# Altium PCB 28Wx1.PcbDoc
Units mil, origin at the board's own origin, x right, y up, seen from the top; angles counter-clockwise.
Board outline 11435 x 885 mil, 2 copper layers (Top Layer, Bottom Layer); 107 components, 53 nets, 262 pads, 0 vias.
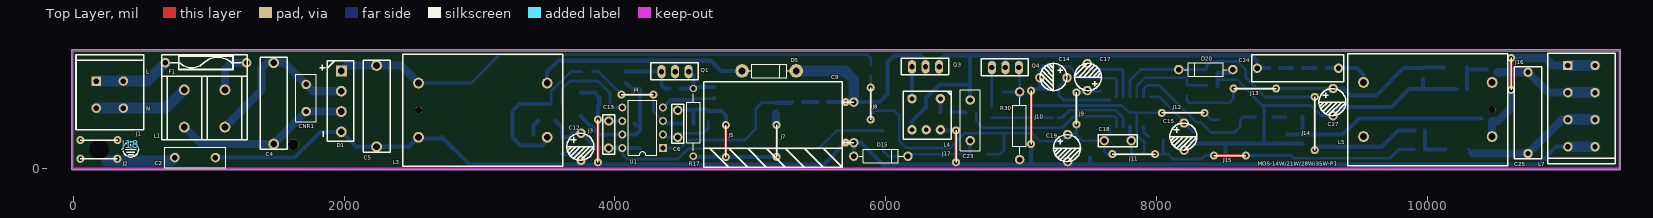
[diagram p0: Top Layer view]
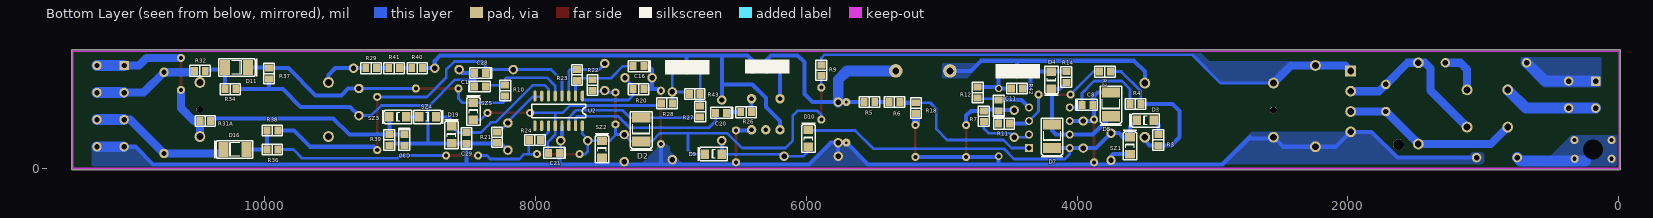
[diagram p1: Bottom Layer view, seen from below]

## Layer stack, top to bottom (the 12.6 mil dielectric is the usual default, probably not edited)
Top Layer: signal copper 1.4
Dielectric: dielectric 12.6, FR-4, Dk 4.8
Bottom Layer: signal copper 1.4

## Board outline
-10,-10 11425,-10 11425,875 -10,875

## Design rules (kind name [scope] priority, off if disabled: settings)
Clearance [All] p1: gap=10
ComponentClearance [All] p1 off: gap=10 collisioncheckmode=3 verticalgap=10 showdistances=FALSE
Height [All] p1 off: minheight=0 maxheight=1000 prefheight=500
PolygonConnect [All] p1: connectstyle=Direct reliefconductorwidth=10 reliefentries=4 polygonreliefangle="90 Angle"
RoutingVias [All] p1: holewidth=28 width=50 viastyle="Through Hole" minholewidth=28 minwidth=50 maxholewidth=28 maxwidth=50
SolderMaskExpansion [All] p1: expansion=4
TestPointUsage [All] p1: valid=0 allowmultiple=FALSE
Testpoint [All] p1: side=15 testpointundercomponent=TRUE minsize=40 maxsize=100 preferedsize=60 minholesize=0 maxholesize=40 preferedholesize=32 testpointgrid=1 style=1023 order=0-112345678
Width [All] p1: maxlimit=80 minlimit=10 preferedwidth=10 toplayer_minwidth=20 toplayer_maxwidth=20 toplayer_prefwidth=20 bottomlayer_prefwidth=30 minimp=50.000000 maximp=50.000000 favimp=50.000000
17 further rules are at their usual default settings.

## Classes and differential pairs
component class 20081212SMD: C1 C2 C4 C5 C6 C8 C9 C11 C12 C13 C14 C15 C16 C17 C18 C19 C20 C21 C23 C24 C25 C27 C28 C29 C30 CNR1 D1 D2 D3 D4 D5 D7 D8 D9 D10 D11 D15 D16 D19 D20 F1 J1 J2 L1 L3 L4 L5 L7 Q1 Q3 Q4 R2 R3 R4 R5 R6 R7 R9 R10 R11 R12 R14 R17 R18 R20 R21 R22 R23 R24 R26 R27 R28 R29 R30 R31A R32 R34 R36 R37 R38 R39 R40 R41 R42 R43 SZ1 SZ2 SZ3 SZ4 SZ5 U1 U2

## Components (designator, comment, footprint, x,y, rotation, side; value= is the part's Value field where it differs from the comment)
C1 "Cap" C0805A 8410,605 r180 bottom
C2 "Cap Y1" RAD-0.3 900,80 r180 top
C4 "Cap X1" RAD0.6B#1 1480,180 r90 top
C5 "CAP" RAD0.6B#1 2240,160 r90 top
C6 "CAP" RAD0.2B 4465,430 r270 top
C8 "CAP" C0805A 3925,470 r180 bottom
C9 "Cap2" RB.3/.6A 5765,490 r0 top locked
C11 "CAP" C0805A 4580,465 r90 bottom
C12 "CAP" RB.2/.2 3750,160 r0 top
C13 "CAP" RAD0.2B 3955,350 r270 top
C14 "Cap" RB.2/.2 7240,670 r270 top
C15 "Cap" RB.2/.2 8205,235 r0 top
C16 "Cap" C0805A 7240,755 r0 bottom
C17 "Cap2" RB.2/.2 7490,675 r180 top
C18 "CAP" RAD0.2B 7815,205 r180 top
C19 "Cap" RB.2/.2 7345,150 r0 top
C20 "CAP" C0805A 6630,410 r0 bottom
C21 "CAP" C0805A 7865,115 r0 bottom
C23 "CAP" RAD-0.3 6625,355 r270 top
C24 "CAP" RAD0.6B#2 9345,740 r180 top
C25 "CAP" RAD0.6B#2 10745,710 r270 top
C27 "Cap2" RB.2/.2 9305,490 r0 top
C28 "Cap" C0805A 8410,705 r0 bottom
C29 "Cap" C0805A 8510,225 r90 bottom
C30 "Cap" C0805A 8970,210 r270 bottom
CNR1 "CNR" RAD-0.2 1720,520 r270 top
D1 "DIODEx4" SIP4C 1980,720 r270 top
D2 "Diode 1N5819" CD4532-1812A 7220,280 r270 bottom
D3 "DIODE" CD3216-1206A 3495,355 r0 bottom
D4 "Comment" CD3216-1206A 4190,655 r270 bottom
D5 "HIGH EFFICIENCY DIODES" DIODE-0.4#1 5140,720 r0 top
D7 "Diode 1N5819" CD4532-1812A 4185,230 r270 bottom
D8 "Diode 1N5819" CD4532-1812A 3750,465 r270 bottom
D9 "DIODE" CD3216-1206A 6685,105 r0 bottom
D10 "DIODE" CD3216-1206A 5985,220 r90 bottom
D11 "DIODE" CD4532-1810 10200,745 r180 bottom
D15 "FFAST RECOVERY RECTIFIER" DIODE-0.4#2 5965,90 r0 top
D16 "Surface Mount Glass Passivated Rectifier" CD4532-1810 10230,140 r0 bottom
D19 "DIODE" CD3216-1206A 8620,245 r90 bottom
D20 "HIGH EFFICIENCY DIODES" DIODE-0.4#2 8365,730 r180 top
F1 "3.15A/250V" FUSE0.6 680,780 r0 top
J1 "Header 2" IDC4-3.8MM 20,840 r270 top
J2 "PAD" GND1 190,140 r180 top
J3 "Comment" JUMP_8MM 3875,45 r90 top
J4 "Comment" JUMP_6MM 4285,545 r180 top
J5 "Comment" JUMP_6MM 4820,320 r270 top
J7 "Comment" JUMP_6MM 5195,85 r90 top
J8 "Comment" JUMP_6MM 5890,360 r90 top
J9 "Comment" JUMP_6MM 7410,325 r90 top
J10 "Comment" JUMP_10MM 7075,180 r90 top
J11 "Comment" JUMP_8MM 7675,105 r0 top
J12 "Comment" JUMP_8MM 8040,410 r0 top
J13 "Comment" JUMP_8MM 8570,590 r0 top
J14 "Comment" JUMP_10MM 9170,135 r90 top
J15 "Comment" JUMP_6MM 8425,95 r0 top
J16 "Comment" JUMP_6MM 10620,580 r90 top
J17 "Comment" JUMP_6MM 6520,45 r90 top
J18 "Comment" GND2 425,180 r0 top
L1 "INDUCTOR_EMI" EE1414H 820,580 r0 top
L3 "INDUCTOR2:2_3_1" EE2520H 2435,15 r0 top
L4 "INDUCTOR2:2" EE0808 6405,515 r180 top
L5 "INDUCTOR2.1_1" EE2720H 9415,20 r0 top locked
L7 "TUBES1" IDC8-3.8MM 11040,760 r270 top locked
Q1 "MOSFET-N" TO-220D 4445,715 r0 top
Q3 "MOSFET-N" TO-220D 6295,750 r0 top
Q4 "MOSFET-N" TO-220D 6885,745 r0 top
R2 "RES1" 2012[0805]A 3795,715 r0 bottom
R3 "RES1" 2012[0805]A 3400,210 r90 bottom
R4 "RES1" 2012[0805]A 3570,475 r0 bottom
R5 "RES1" 2012[0805]A 5535,490 r0 bottom
R6 "RES1" 2012[0805]A 5350,490 r0 bottom
R7 "Res1" 2012[0805]A 4690,385 r270 bottom
R9 "RES1" 2012[0805]A 5890,725 r90 bottom
R10 "RES1" 2012[0805]A 8225,575 r90 bottom
R11 "RES1" 2012[0805]A 4540,330 r0 bottom
R12 "RES1" 2012[0805]A 4735,560 r90 bottom
R14 "RES1" 2012[0805]A 4080,675 r90 bottom
R17 "RES1" AXIAL-0.5#1 4580,340 r90 top
R18 "RES1" 2012[0805]A 5190,445 r90 bottom
R20 "RES1" 2012[0805]A 7240,585 r0 bottom
R21 "RES1" 2012[0805]A 8285,230 r90 bottom
R22 "RES1" 2012[0805]A 7580,615 r270 bottom
R23 "RES1" 2012[0805]A 7695,690 r90 bottom
R24 "RES1" 2012[0805]A 8005,210 r180 bottom
R26 "RES1" 2012[0805]A 6445,415 r0 bottom
R27 "RES1" 2012[0805]A 6785,420 r90 bottom
R28 "RES1" 2012[0805]A 7030,480 r0 bottom
R29 "Res1" 2012[0805]A 9215,740 r180 bottom
R30 "RES1" AXIAL-0.5#2 6990,315 r90 top
R31A "RES1" 2012[0805]A 10440,350 r0 bottom
R32 "RES1" 2012[0805]A 10480,720 r180 bottom
R34 "RES1" 2012[0805]A 10255,585 r0 bottom
R36 "RES1" 2012[0805]A 9945,140 r180 bottom
R37 "RES1" 2012[0805]A 9970,700 r90 bottom
R38 "RES1" 2012[0805]A 9945,280 r180 bottom
R39 "RES1" 2012[0805]A 9080,210 r90 bottom
R40 "Res1" 2012[0805]A 8875,740 r0 bottom
R41 "Res1" 2012[0805]A 9045,740 r180 bottom
R42 "RES1" 2012[0805]A 4445,590 r0 bottom
R43 "RES1" 2012[0805]A 6825,550 r0 bottom
SZ1 "Zener" CD3216-1206A 3610,165 r90 bottom
SZ2 "Zener" CD3216-1206A 7510,140 r90 bottom
SZ3 "Zener" CD3216-1206A 9015,380 r0 bottom
SZ4 "Zener" CD3216-1206A 8800,380 r180 bottom
SZ5 "Zener" CD3216-1206A 8460,420 r90 bottom
U1 "59039" DIP-8 4205,300 r90 top
U2 "IC" DIP16A 7655,535 r0 bottom

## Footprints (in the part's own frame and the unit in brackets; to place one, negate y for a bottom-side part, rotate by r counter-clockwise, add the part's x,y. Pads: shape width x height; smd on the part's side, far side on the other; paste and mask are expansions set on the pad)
2012[0805]A [mm] "Chip Resistor; Body 2.0 x 1.3 mm (LxW typ)"
  rect 1.3x1.5 smd: 1(-1.016,0) 2(1.016,0)
  silkscreen extent -1.91,-1.02 1.91,1.02
AXIAL-0.5#1 [mm] "Variable Resistor; 2 Leads"
  round 1.4 hole 0.85: 1(-6.35,0) 2(6.35,0)
  silkscreen extent -5.33,-1.27 5.33,1.27
AXIAL-0.5#2 [mm] "Semiconductor Resistor; 2 Leads"
  round 1.778 hole 1.016: 1(-6.35,0) 2(6.35,0)
  silkscreen extent -5.33,-1.27 5.33,1.27
C0805A [mm] "Chip Capacitor; Body 2.0 x 1.2 mm (LxW typ)"
  rect 1.3x1.5 smd: 1(-1.016,0) 2(1.016,0)
  silkscreen extent -2.16,-1.02 1.91,1.02
CD3216-1206A [mm] "Chip Diode; Body 3.2 x 1.6 mm (LxW typ)"
  rect 1.6x1.8 smd: 1(-1.524,0) 2(1.651,0)
  silkscreen extent -2.54,-1.27 2.92,1.27
CD4532-1810 [mm] "Chip Diode; Body 4.5 x 3.2 mm (LxW typ)"
  rect 1.9x2.8 smd: 1(-2.413,0) 2(1.95,0)
  silkscreen extent -3.56,-1.65 3.56,1.65
CD4532-1812A [mm] "Chip Diode; Body 4.5 x 3.2 mm (LxW typ)"
  rect 1.9x3.4 smd: 1(-2.413,0) 2(2.032,0)
  silkscreen extent -3.56,-2.03 3.68,2.03
DIODE-0.4#1 [mil] "Tunnel Diode - Dependent Source Model; 2 Leads"
  round 100 hole 50: 1(-200,0) 2(200,0)
  silkscreen extent -160,-50 160,50
DIODE-0.4#2 [mil] "Tunnel Diode - Dependent Source Model; 2 Leads"
  round 70 hole 40: 1(-200,0) 2(200,0)
  silkscreen extent -160,-50 160,50
DIP16A [mil]
  oval 24x80 smd: 0(350,0) 0(350,220) 1(0,0) 2(50,0) 3(100,0) 4(150,0) 5(200,0) 6(250,0) 7(300,0) 8(300,220) 9(250,220) 10(200,220) 11(150,220) 12(100,220) 13(50,220) 14(0,220)
  silkscreen extent -25,60 375,160
DIP-8 [mm] "DIP; 8 Leads; Row Spacing 7.62 mm; Pitch 2.54 mm"
  rect 1.5x1.5 hole 0.9: 1(-3.81,-3.81)
  round 1.5 hole 0.9: 2(-1.27,-3.81) 3(1.27,-3.81) 4(3.81,-3.81) 5(3.81,3.81) 6(1.27,3.81) 7(-1.27,3.81) 8(-3.81,3.81)
  silkscreen extent -5.15,-2.65 5.15,2.65
EE0808 [mil]
  round 70 hole 35: 1(0,0) 3(210,0) 4(210,230) 5(105,230) 6(0,230)
  silkscreen extent -80,-55 275,300
EE1414H [mil]
  round 80 hole 50: 1(0,0) 2(0,-275) 3(300,-275) 4(300,0)
  silkscreen extent -165,-370 465,261
EE2520H [mil]
  round 80 hole 50: 1(1065,215) 3(1065,615) 4(115,615) 6(115,215)
  round 50 hole 50: 5(115,415)
  silkscreen extent 0,0 1181,827
EE2720H [mil]
  round 80 hole 50: 1(1065,215) 3(1065,615) 4(115,615) 6(115,215)
  round 50 hole 50: 2(1065,415)
  silkscreen extent 0,0 1181,827
FUSE0.6 [mil]
  round 70 hole 40: 1(0,0) 2(600,0)
  silkscreen extent 40,-50 560,50
GND1 [mil] "GND"
  round 60 hole 145: 0(0,0)
  round 60 hole 30: ""(-137.8,-68.9) ""(-135,68.9) ""(137.8,-68.9) ""(137.8,68.9)
  silkscreen extent -138,-69 138,69
GND2 [mil]
  silkscreen extent -57,-97 57,17
IDC4-3.8MM [mil]
  round 70 hole 40: 1(195,350) 2(395,350) 2(395,150)
  rect 70x70 hole 40: 1(195,150)
  silkscreen extent 0,0 555,500
IDC8-3.8MM [mil]
  round 70 hole 40: 1(0,200) 2(200,200) 2(200,0) 3(400,200) 3(400,0) 4(600,0) 4(600,200)
  rect 70x70 hole 40: 1(0,0)
  silkscreen extent -90,-150 725,350
JUMP_6MM [mil]
  round 60 hole 30: 1(0,0) 2(236.22,0)
  silkscreen extent 0,0 236,0
JUMP_8MM [mil]
  round 60 hole 30: 1(0,0) 2(314.96,0)
  silkscreen extent 0,0 315,0
JUMP_10MM [mil]
  round 60 hole 30: 1(0,0) 2(393.7,0)
  silkscreen extent 0,0 394,0
RAD0.2B [mil]
  round 70 hole 40: 1(0,0) 2(200,0)
  silkscreen extent -45,-45 245,45
RAD0.6B#1 [mil]
  round 80 hole 50: 1(0,0) 2(600,0)
  silkscreen extent -40,-100 640,100
RAD0.6B#2 [mil]
  round 70 hole 40: 1(0,0) 2(600,0)
  silkscreen extent -40,-100 640,100
RAD-0.2 [mil] "Jumper Wire; 2 Leads"
  round 70 hole 40: 1(-100,0) 2(100,0)
  silkscreen extent -175,-75 175,75
RAD-0.3 [mil] "Capacitor; 2 Leads"
  round 70 hole 40: 1(-150,0) 2(150,0)
  silkscreen extent -225,-75 225,75
RB.2/.2 [mil]
  round 70 hole 40: 1(0,100) 2(0,-100)
  silkscreen extent -105,-100 95,100
RB.3/.6A [mil]
  round 70 hole 40: 1(0,0) 2(0,-300)
  silkscreen extent -1110,-480 0,150
SIP4C [mil]
  rect 80x80 hole 50: 1(0,0)
  round 80 hole 50: 2(150,0) 3(300,0) 4(450,0)
  silkscreen extent -75,-160 520,92
TO-220D [mil]
  oval 60x100 hole 40: 1(0,0) 2(-100,0) 3(100,0)
  silkscreen extent -180,-60 170,65

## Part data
C1 C6 C8 C11 C13 C16 C18 C20 C21 C28 C29 C30: "Ceramic Capacitor"
C2: library part CAP, "Y Capacitor"
C4: library part CAP, "BOX Capacitor"
C5: "BOX Capacitor"
C9 C17 C27: "Electrolytic Capacitor"
C12 C14 C15 C19: library part Cap2, "Electrolytic Capacitor"
C23 C24 C25: "POLYPROPYLENE FILM Capacitor"
CNR1: "Varistor"
D1: "Bridge Diode"
D2 D7 D8: library part "Diode 1N4007", "1 Amp General Purpose Rectifier"
D3 D9 D10 D19: "Diode  75V,1A"
D5: library part DIODE, "Diode HIGH EFFICIENCY RECTIFIERS 600V, 3A"
D11: "Diode FAST RECOVERY RECTIFIER 700V,1A"
D15 D16: library part DIODE, "Diode FAST RECOVERY RECTIFIER 700V,1A"
D20: library part DIODE, "Diode HIGH EFFICIENCY RECTIFIERS 600V, 1A"
F1: library part FUSE2, "Fuse"
J1: "Header, 2-Pin"
L1: "EE19H Inductor"
L4: "EE08 Inductor"
L7: "Jumper Wire Pin spacing 3.5mm    235-107/000-009"
Q1: "Transistor, MOSFET  600V, 11A"
Q3 Q4: "Transistor, MOSFET  600V, 6A"
R2 R3 R4 R5 R6 R9 R10 R11 R12 R14 R18 R20 R21 R22 R23 R24 R26 R27 R28 R29 R31A R32 R34 R36 R37 R38 R39 R40 R41 R42 R43: "Resistor 1/4W"
R7: "Resistor"
R17 R30: "Resistor 1W"
SZ1 SZ2: library part "D Zener", "Zener Diode"
SZ3 SZ4 SZ5: library part "D Zener", "Zener Diode 1/4W"
U1: "M8128"
U2: library part M8145, "IC, Ballast Driver"

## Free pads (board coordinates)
  round 80 hole 80: 0(1625,175)
  round 60 hole 20: 0(5705,490) 1(5705,190)

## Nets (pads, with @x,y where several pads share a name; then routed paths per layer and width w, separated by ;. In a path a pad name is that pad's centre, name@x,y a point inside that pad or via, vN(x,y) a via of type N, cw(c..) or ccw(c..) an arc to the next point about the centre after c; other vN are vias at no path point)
GND: C1.1 C2.1 C5.1 C6.1 C8.2 C9.2 C11.1 C12.2 C13.1 C14.2 C15.2 C16.1 C18.1 C19.2 C21.1 C27.2 C28.2 C29.1 C30.2 D1.4 D8.1 D15.1 D19.1 D20.1 J3.1 J3.2 J5.1 J5.2 J7.1 J7.2 J10.1 J10.2 J17.1 J17.2 L3.6 L4.6 L7.4 pad.1 R7.1 R11.2 R17.1 R18.1 R20.1 R21.1 R30.1 R34.1 R37.1 R39.1 SZ1.1 SZ2.1 U1.6 U2.11 | length 18896.5
  Top Layer w20: J3.1 J3.2 ; J5.2 J5.1 ; J7.1 J7.2 ; J17.1 J17.2 ; J10.1 J10.2
  Bottom Layer w20: C21.1@7815,115 C18.1 ; 8450,655 8595,655 8785,465 8795,465 ; 8795,185 8795,465 ; C27.2 9215,390 9140,465 8795,465
  Bottom Layer w30: C2.1 1635,80 1825,270 D1.4 2090,160 C5.1 2480,160 L3.6 ; L3.6@2545,220 2720,220 ; 2725,230 2925,30 4585,30 ; SZ1.1 3735,105 3750,90 C12.2 ; D8.1 3850,560 3885,525 C8.2@3885,475 ; C8.2 C8.2@3885,475 ; U1.6 C13.1 3884.96,350 J3.2 3875,465 C8.2@3885,475 ; C6.1 C11.1@4580,430 ; R11.2 C11.1@4580,430 ; J5.1 4820,390 4785,425 R7.1 4680,435 4585,435 C11.1@4580,430 ; J7.2@5190,326.22 J7.2 ; J7.1@5193.78,83.78 J5.2 4586.22,83.78 R17.1 4580,35 4585,30 ; D15.1 C9.2 ; L4.6 6408.78,281.22 J17.2 ; R30.1 6990,30 ; J10.1 7075,30 ; J10.2@7075,585 7140,585 ; 7140,30 7075,30 ; R20.1 7140,585 ; C16.1 7165,755 7140,730 C14.2 7140,585 ; 7465,30 7405,30 ; SZ2.1 7510,30 ; C18.1@7805,205 U2.11@7805,310 ; C21.1 7825,30 ; C15.2 8255,185 C29.1 ; C1.1 8450,655 C28.2 8545,705 D20.1@8570,730 ; R39.1@9080,180 9075,185 8795,185 D19.1 C29.1 ; C27.2 9370,455 9735,455 9865,585 9970,585 ; R37.1 9970,585 ; R34.1 9970,585 ; L7.4@11040,160 10955,160 10825,30 8515,30 ; 4585,30 5545,30 pad.1 C9.2 ; C9.2 5820,190 5980,30 6990,30 ; 6990,30 7075,30 ; 6990,30 7075,30 ; 7075,30 7405,30 ; 7405,30 7510,30 ; 7510,30 7825,30 ; 7825,30 8515,30 ; C29.1 8510,35 8515,30
  Bottom Layer w60: J7.2@5190,326.22 R18.1
  Bottom Layer w80: L7.4@11045,160 L7.4@11240,160
L: F1.1 J1.1 | length 565.9
  Bottom Layer w80: J1.1@170,645 370,645 545,645 F1.1
N: J1.2 L1.1 | length 705.9
  Bottom Layer w80: J1.2@170,445 370,445 685,445 L1.1
NetC1_2: C1.2 R10.2 U2.5 | length 669
  Bottom Layer w20: U2.5@7855,530 7855,610 7915,670 8215,670 8225,660 R10.2 C1.2@8370,615
NetC2_2: C2.2 J2. J2.0 | length 607.3
  Bottom Layer w30: J2.0@180,120 245,55
  Bottom Layer w80: 245,55 725,55 C2.2
NetC4_1: C4.1 CNR1.2 D1.3 L1.2 | length 1311.2
  Bottom Layer w60: L1.2 945,180 C4.1 CNR1.2 D1.3
NetC5_2: C5.2 D1.1 L3.4 R9.2 | length 4127.8
  Bottom Layer w20: L3.4 2940,630 3150,840 5865,840 5890,815 R9.2
  Bottom Layer w60: D1.1 2020,760 C5.2 2420,760 L3.4
NetC6_2: C6.2 R7.2 U1.2 | length 420.2
  Bottom Layer w20: U1.2 4375,230 C6.2 4495,260 4655,260 4690,295 R7.2
NetC8_1: C8.1 R4.2 U1.5 | length 710.4
  Bottom Layer w20: R4.2 3610,585 3670,645 3875,645 3965,555 C8.1
  Bottom Layer w30: C8.1 3985,450 U1.5
NetC9_1: C9.1 D5.2 pad.0@5705,490 Q3.1 R5.2 | length 1692
  Bottom Layer w30: R5.2 C9.1 5955,490 6015,550 6015,785 6065,835 6260,835 6295,800 Q3.1@6295,740
  Bottom Layer w80: D5.2 5700,720 5765,655 C9.1
NetC11_2: C11.2 R12.1 U1.4 | length 399.9
  Bottom Layer w20: C11.2@4585,515 R12.1@4730,515
  Bottom Layer w30: U1.4 4410,505 C11.2 ; R12.1@4730,515 R12.1
NetC12_1: C12.1 C13.2 D3.2 D7.2 D10.2 SZ1.2 U1.8 | length 2852.3
  Bottom Layer w20: U1.8 4055,105 4090,70 4465,70 4540,145 5505,145 5640,280 5975,280 D10.2@5980,275
  Bottom Layer w30: D3.2 3610,305 SZ1.2 3660,230 3690,260 C12.1 3860,150 C13.2 U1.8 D7.2
NetC14_1: C14.1 R20.2 U2.1 | length 544.4
  Bottom Layer w20: C14.1 7280,610 R20.2 7280,540 7315,505 U2.1@7655,505
NetC15_1: C15.1 R21.2 U2.0@8005,535 U2.7 | length 440.6
  Bottom Layer w20: U2.7@7955,530 8020,530 C15.1@8210,340 ; C15.1 8270,270 R21.2
NetC16_2: C16.2 R22.1 R23.1 U2.2 | length 572.3
  Bottom Layer w20: C16.2 7355,755 7445,665 R23.1@7695,665 ; U2.2@7705,530 R23.1@7705,650
NetC17_2: C17.2 R23.2 U2.3 | length 475.7
  Bottom Layer w20: C17.2@7490,770 7530,730 R23.2 7745,730 7755,720 U2.3@7755,530
NetC20_1: C20.1 R26.2 | length 107.1
  Bottom Layer w30: R26.2 6585,415 C20.1
NetC20_2: C20.2 U2.13 | length 1252.5
  Bottom Layer w20: C20.2 6670,350 ; 6695,325 6670,350 ; U2.13@7705,310 7705,370 7690,385 7390,385 7305,300 6720,300 6670,350
NetC21_2: C21.2 J12.1 J12.2 R28.2 SZ5.1 U2.10 | length 1788.3
  Top Layer w20: J12.1 J12.2
  Bottom Layer w20: R28.2@7070,465 7745,465 7800,410 7855,410 ; 7855,275 U2.10@7855,310 ; C21.2 7910,120 7910,195 7855,250 U2.10@7855,310 ; J12.1 7855,410 ; J12.2 8404.96,360 SZ5.1 ; U2.10@7855,310 7855,410
NetC23_1: C23.1 C24.2 L4.4 Q3.3 Q4.1 R40.1 | length 3643.1
  Bottom Layer w30: L4.4 6195,350 6300,455 6300,520 6400,620 6625,620 ; Q3.3@6395,745 6395,795 6435,835 6625,835 ; C23.1 6625,835 ; Q4.1 6885,835 ; R40.1 C24.2 8745,795 8705,835 6625,835
NetC23_2: C23.2 D9.1 D10.1 D15.2 | length 765.7
  Bottom Layer w20: D10.1 5985,125 6020,90 D15.2 6180,105 D9.1@6595,105
  Bottom Layer w30: D9.1 C23.2
NetC24_1: C24.1 L5.4 R29.1 | length 350.7
  Bottom Layer w30: R29.1 C24.1 9480,740 9530,690 L5.4
NetC25_1: C25.1 L7.2 R32.1 | length 782.1
  Bottom Layer w60: R32.1@10520,710 10730,710 C25.1 10895,560 L7.2@11040,560
  Bottom Layer w80: L7.2@11040,560 L7.2@11240,560
NetC25_2: C25.2 D16.2 L7.3 | length 1049.2
  Bottom Layer w20: D16.2 D16.2@10336.77,110
  Bottom Layer w60: D16.2@10336.77,110 C25.2 10995,360 L7.3@11040,360
  Bottom Layer w80: L7.3@11040,360 L7.3@11240,360
NetC27_1: C27.1 D11.2 J13.1 J13.2 R10.1 R37.2 SZ5.2 | length 2132.5
  Top Layer w20: J13.1 J13.2
  Bottom Layer w20: R10.1 8225,500 8240,485 SZ5.2 8540,485 8570,515 J13.1 ; J13.2 C27.1 ; R37.2 R37.2@9975,745
  Bottom Layer w30: C27.1 9385,590 9435,540 9625,540 9825,740 R37.2 ; R37.2@9975,745 D11.2
NetC28_1: C28.1 D20.2 J14.1 J14.2 R38.2 U2.4 | length 2894.4
  Top Layer w20: J14.1 J14.2
  Bottom Layer w20: U2.4@7805,530 7805,650 7885,730 8160,730 D20.2@8170,740 ; D20.2@8170,730 8370,730 8370,755 8405,790 8600,790 8660,730 8660,670 8802.5,527.5 J14.2@9170,527.5
  Bottom Layer w30: J14.1 9195,160 9665,160 9785,280 R38.2
NetC29_2: C29.2 D19.2 SZ4.2 U2.6 | length 1119.3
  Bottom Layer w20: U2.6@7905,530 7905,585 7935,615 8020,615 8295,340 8330,340 8405,265 C29.2 8575,265 D19.2 8620,360 8640,380 SZ4.2
NetC30_1: C30.1 R31A.1 R39.2 SZ3.2 | length 1584.7
  Bottom Layer w30: C30.1 R39.2 SZ3.2 ; R39.2@9105,250 9375,250 9495,370 R31A.1@10400,370
NetCNR1_1: C4.2 CNR1.1 D1.2 L1.3 | length 1350.4
  Bottom Layer w60: L1.3 1390,575 ; 1390,685 1390,575 ; D1.2 1770,570 CNR1.1 1560,780 C4.2 1430,780 1390,740 1390,575
NetD2_1: D2.1 R27.1 U2.12 | length 1040.6
  Bottom Layer w20: R27.1@6785,375 D2.1@7235,375 ; D2.1@7275,375 7305,375 7360,430 7700,430 7755,375 U2.12@7755,310
NetD3_1: D3.1 R3.2 | length 119.5
  Bottom Layer w30: R3.2 3400,320 D3.1
NetD4_1: D4.1 Q1.2 R14.2 R42.1 | length 435.4
  Bottom Layer w30: R14.2 D4.1 Q1.2 4345,615 4370,590 R42.1
NetD4_2: D4.2 D7.1 D8.2 R14.1 U1.7 | length 998.2
  Bottom Layer w30: D8.2 3885,250 U1.7 ; 4005,250 U1.7 ; R14.1 4130,585 4185,585 D7.1 4185,280 4155,250 U1.7 ; D7.1@4145,330 D7.1@4155,320
NetD5_1: D5.1 L3.3 Q1.1 | length 1676.3
  Bottom Layer w30: L3.3 3500,715 3580,795 4445,795 ; Q1.1 4445,795 ; D5.1@4945,715 D5.1 4785,720 4710,795 4445,795
NetD11_1: D11.1 R32.2 R34.2 | length 305
  Bottom Layer w30: R34.2 D11.1 ; D11.1@10295,730 R32.2@10440,730
NetD16_1: D16.1 R36.1 R38.1 | length 290
  Bottom Layer w30: R38.1 R36.1 D16.1
NetF1_2: F1.2 L1.4 | length 330.7
  Bottom Layer w60: L1.4 1120,730 1170,780 F1.2
NetL3_1: L3.1 R2.1 R3.1 R4.1 | length 1180.1
  Bottom Layer w20: R4.1 3530,570 3675,715 R2.1
  Bottom Layer w30: L3.1 3500,205 3465,170 R3.1 3305,170 3245,230 3245,425 3295,475 R4.1@3510,475
NetL4_1: L4.1 R26.1 | length 100
  Bottom Layer w30: R26.1 L4.1
NetL4_3: L4.3 Q3.2 | length 230
  Bottom Layer w30: L4.3 Q3.2@6195,745
NetL5_1: J16.1 J16.2 L5.1 L7.1 R31A.2 | length 1293.9
  Top Layer w20: J16.1 J16.2
  Bottom Layer w60: L5.1 R31A.2@10480,335 ; R31A.2 10525,350 10620,445 J16.1 ; J16.2 10873.78,816.22 10930,760 L7.1@11040,760
  Bottom Layer w80: L7.1@11040,760 L7.1@11240,760
NetQ1_3: Q1.3 R12.2 R17.2 R42.2 | length 394.5
  Bottom Layer w30: R42.2 R17.2 R17.2@4580,600 ; Q1.3@4545,720 4580,685 R17.2@4580,600 ; R12.2 R17.2@4580,600
NetQ4_2: Q4.2 R27.2 R43.1 | length 275
  Bottom Layer w20: R27.2 R43.1 Q4.2@6785,735
NetQ4_3: Q4.3 R28.1 R30.2 R43.2 | length 395
  Bottom Layer w20: R43.2@6865,565 R30.2 ; R28.1 R30.2 ; Q4.3@6990,750 R30.2
NetR2_2: J4.1 J4.2 R2.2 R11.1 U1.3 | length 897.7
  Top Layer w20: J4.2 J4.1
  Bottom Layer w20: R2.2 3878.78,715 J4.2 ; J4.1 4285,420 U1.3
  Bottom Layer w30: U1.3 4375,330 R11.1
NetR5_1: R5.1 R6.2 | length 105
  Bottom Layer w30: R6.2 R5.1
NetR6_1: R6.1 R18.2 U1.1 | length 1183.7
  Bottom Layer w20: U1.1 4485,150 4545,210 4960,210 5040,290 5040,440 5085,485 R18.2
  Bottom Layer w30: R18.2 5305,485 R6.1
NetR22_1: 
NetR24_2: R24.2 U2.9 | length 89.5
  Bottom Layer w20: U2.9@7905,310 7905,270 R24.2@7940,235
NetR29_2: R29.2 R41.1 | length 90
  Bottom Layer w30: R41.1 R29.2
NetR40_2: R40.2 R41.2 | length 90
  Bottom Layer w30: R40.2 R41.2
NetSZ3_1: SZ3.1 SZ4.1 | length 95
  Bottom Layer w20: SZ4.1 SZ3.1
VCC: C17.1 C18.2 C19.1 D2.2 D9.2 J8.1 J8.2 J9.1 J9.2 J11.1 J11.2 J15.1 J15.2 R9.1 R22.2 R24.1 R36.2 SZ2.2 U2.14 | length 5947.1
  Top Layer w20: J8.1 J8.2 ; J9.1 J9.2 ; J11.1 J11.2 ; J15.1 J15.2
  Bottom Layer w20: J8.1 5890,395 5920,425 6065,425 6100,390 6100,255 ; J8.2 R9.1 ; 6100,275 6100,255 ; D9.2 6845,105 6875,135 6875,260 ; J9.1 7410,255 7405,250 ; J9.2 7481.22,561.22 7490,570 R22.2@7585,570 ; U2.14@7655,310 7655,255 C18.2@7605,205 ; J11.1 7635,105 7615,125 C18.2 ; R24.1@8050,210 8050,105 J11.2 8085,105 8120,70 8335,70 8360,95 8415,95 J15.1@8425,105 ; J15.2 8995,95 9015,75 9725,75 9790,140 R36.2 ; 6100,255 6100,205 6155,150 6475,150 6585,260 6875,260 ; 6875,260 7080,260 7140,200 7295,200 C19.1 7405,250 ; 7405,250 7450,205 SZ2.2 C18.2@7605,205 ; C18.2@7605,205 C18.2 ; C18.2@7605,205 C18.2
pads on no net: L3.5 L4.5 L5.2 L5.3 L5.6 U2.0@8005,315 U2.8

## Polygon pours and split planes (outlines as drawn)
GND on Bottom Layer "Bottom Layer-No Net" (solid, pour order 1001): 11040,160 10945,160 10800,15 11265,15 ccw(c11265,30) 11280,30 11280,160 11040,160
GND on Bottom Layer "Bottom Layer-No Net" (solid, pour order 1000): 7075,180 7225,30 6910,30 7010,130 7010,160 7030,180 7075,180
GND on Bottom Layer "Bottom Layer-No Net" (solid, pour order 1002): 5530,15 5705,190 5820,190 5820,180 5985,15 5530,15
GND on Bottom Layer "Bottom Layer-No Net" (solid, pour order 1001): 1050,80 1635,80 1825,270 2710,270 2950,30 1025,30 cw(c1025,60) 995,60 995,100 cw(c1015,100) 1015,120 1075,120 cw(c1075,100) 1095,100 1095,90 cw(c1085,90) 1085,80 1050,80
NetC5_2 on Bottom Layer "Bottom Layer-No Net" (solid, pour order 1000): 3155,850 3085,850 3040,805 3025,790 2410,790 2570,630 2955,630 3160,835 3160,840
L on Bottom Layer "Bottom Layer-No Net" (solid, pour order 1001): 680,820 135,820 130,815 130,610 140,600 145,600 555,600 725,770 725,815 720,820 680,820
NetC2_2 on Bottom Layer "Bottom Layer-No Net" (solid, pour order 1000): 280,15 30,15 cw(c30,35) 10,35 10,230 cw(c25,230) 25,245 350,245 580,15 280,15
NetD5_1 on Bottom Layer "Bottom Layer-No Net" (solid, pour order 1000): 4943.04,775 4750.78,775 4730,753 4813.14,665 4943.04,665 4989.8,665 4995,670.5 4995,769.5 4989.8,775 4943.04,775

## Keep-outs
Keep-Out Layer:
  lines w10: -5,0 -5,866.14 11417.32,866.14 11417.32,0 -5,0

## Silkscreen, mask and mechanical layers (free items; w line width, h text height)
Top Overlay:
  text "L" at 540,700 h30
  text "N" at 540,425 h30
  text "MOS-14W/21W/28W/35W-P1" at 8750,20 h30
